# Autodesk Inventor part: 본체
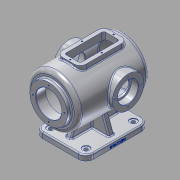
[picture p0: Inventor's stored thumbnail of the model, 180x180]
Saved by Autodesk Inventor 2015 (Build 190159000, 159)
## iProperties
Created: 2021-11
Part Number: 본체
Material: 알루미늄 6061
Document SubType Name: Modeling
Designer: 102879
Density: 2.7 g/cm^3
Appearance: 알루미늄 - 평지
Mass: 3642.31 g
Surface Area: 2489.08 cm^2
Volume: 1349 cm^3
Author: 102879
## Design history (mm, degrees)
sketch "스케치3"
  geometry: L1 (-100, 65)-(-100, 0); L2 (75.993, 65)-(-100, 65); L3 (-100, 0)-(100, 0); A1 r 100 centre (0, 0) between (100, 0) and (75.993, 65); 1 further point
  constraints: 6 end point, 2 horizontal, 2 point on circle, 1 centre point, 1 coincident, 1 midpoint, 1 vertical
  dimensions: "d5" = 100 radius of A1; "d6" = 65 distance from line of point (0, 0) L2; "d10" = 200 dimension on A1 L1
revolve "회전1" sketch "스케치3" stored, may be unused: angle "d11" = 90 deg
sketch "스케치4"
  geometry: C1 r 65 at (0, 0) reference; C2 r 47.5 at (0, 0)
  constraints: 1 centre point, 1 coincident
  dimensions: "d12" = 95 diameter of C2
extrude "돌출2" join sketch "스케치4" distance "d13" = 10; taper "d14" = 0 deg
node "작업 평면1"
sketch "스케치5"
  geometry: L1 (-30, -60)-(30, -60); L2 (30, -60)-(30, 60); L3 (30, 60)-(-30, 60); L4 (-30, 60)-(-30, -60); L5 (-47.5, -110)-(47.5, -110) reference; 1 further point
  constraints: 8 end point, 2 parallel, 1 horizontal, 1 perpendicular
  dimensions: "d16" = 120 distance of L3.end L1.start; "d17" = 60 distance of L1.start L1.end; "d18" = 30 distance from line of L4 point (0, 0); "d26" = 50 distance between parallel lines of L5 L1
extrude "돌출3" join sketch "스케치5" stored distance "d20" = 10; taper "d21" = 0 deg
node "작업 평면2"
sketch "스케치8"
  geometry: L1 (-110, 47.5)-(-100, 47.5) reference; L2 (-100, 47.5)-(-100, 65) reference; L3 (-100, 65)-(-60, 65) reference; L4 (-60, 65)-(-60, 70) reference; L5 (-60, 70)-(60, 70) reference; L6 (60, 70)-(60, 65) reference; L7 (60, 65)-(75.993, 65) reference; L8 (75.993, -65)-(-100, -65) reference; L9 (-100, -65)-(-100, -47.5) reference; L10 (-100, -47.5)-(-110, -47.5) reference; L11 (-110, -47.5)-(-110, 47.5) reference; C1 r 40 at (17, 0); A1 r 100 centre (0, 0) between (75.993, -65) and (75.993, 65) reference; 1 further point
  constraints: 1 centre point, 1 horizontal alignment
  dimensions: "d28" = 80 diameter of C1; "d29" = 127 distance from line of L11 C1.centre
extrude "돌출5" join sketch "스케치8" stored distance "d30" = 150; taper "d31" = 0 deg
sketch "스케치9"
  geometry: L1 (-65, -80)-(65, -80); L2 (65, -80)-(65, 80); L3 (65, 80)-(-65, 80); L4 (-65, 80)-(-65, -80); L5 (-30, -60)-(30, -60) reference; L6 (30, 60)-(-30, 60) reference; 1 further point
  constraints: 8 end point, 2 parallel, 1 horizontal, 1 perpendicular
  dimensions: "d32" = 160 distance of L1.end L2.end; "d33" = 130 distance of L1.start L1.end; "d34" = 65 distance from line of point (0, 0) L2; "d35" = 20 distance between parallel lines of L5 L1; "d36" = 20 distance between parallel lines of L6 L3 (derived)
extrude "돌출6" join sketch "스케치9" distance "d37" = 14; taper "d38" = 0 deg
node "작업 평면3"
sketch "스케치10"
  geometry: L1 (51.397, 114)-(78.603, 114); L2 (78.603, 114)-(115, 14); L3 (130, 14)-(0, 14) reference; L4 (51.397, 114)-(15, 14); L5 (15, 14)-(115, 14); L6 (0, 0)-(0, 14) reference; L7 (130, 0)-(130, 14) reference; 1 further point
  constraints: 8 end point, 2 collinear, 1 horizontal, 1 midpoint
  dimensions: "d41" = 100 distance of L2.end L4.end; "d42" = 20 deg angle of L4 L6; "d43" = 20 deg angle of L7 L2; "d44" = 50 horizontal distance of point (65, 114) L2.end
extrude "돌출7" join sketch "스케치10" stored distance "d45" = 14; taper "d46" = 0 deg
sketch "스케치11"
  geometry: L1 (-23.603, 0)-(-60, -100); L2 (-23.603, 0)-(23.603, 0); L3 (23.603, 0)-(60, -100); L4 (-60, -100)-(60, -100); L5 (80, -100)-(-80, -100) reference; L6 (7, -100)-(7, -55.515) reference; 1 further point
  constraints: 8 end point, 2 horizontal, 1 collinear, 1 midpoint
  dimensions: "d47" = 120 distance of L1.end L3.end; "d48" = 110 deg angle of L5 L3; "d49" = 110 deg angle of L5 L1; "d50" = 53 distance from line of L6 L3.end
extrude "돌출8" join sketch "스케치11" stored distance "d51" = 14; taper "d52" = 0 deg
sketch "스케치12"
  geometry: L1 (-110, 47.5)-(-100, 47.5) reference; L2 (-100, 47.5)-(-100, 65) reference; L3 (-100, 65)-(-60, 65) reference; L4 (-60, 65)-(-60, 70) reference; L5 (-60, 70)-(60, 70) reference; L6 (60, 70)-(60, 65) reference; L7 (60, 65)-(75.993, 65) reference; L8 (75.993, -65)-(47.261, -65) reference; L9 (47.261, -65)-(60, -100) reference; L10 (60, -100)-(80, -100) reference; L11 (80, -100)-(80, -114) reference; L12 (80, -114)-(-80, -114) reference; L13 (-80, -114)-(-80, -100) reference; L14 (-80, -100)-(-60, -100) reference; L15 (-60, -100)-(-47.261, -65) reference; L16 (-47.261, -65)-(-100, -65) reference; L17 (-100, -65)-(-100, -47.5) reference; L18 (-100, -47.5)-(-110, -47.5) reference; L19 (-110, -47.5)-(-110, 47.5) reference; L20 (71.239, 55)-(-85, 55); L21 (-85, 55)-(-85, 0); L22 (-85, 0)-(90, 0); A1 r 100 centre (0, 0) between (75.993, -65) and (75.993, 65) reference; A2 r 90 centre (0, 0) between (90, 0) and (71.239, 55)
  constraints: 6 end point, 2 horizontal, 2 point on circle, 1 centre point, 1 perpendicular, 1 point on line
  dimensions: "d53" = 10 radial gap between concentric circles of A1 A2; "d54" = 10 distance between parallel lines of L7 L20; "d55" = 25 distance between parallel lines of L19 L21
revolve "회전2" sketch "스케치12" stored, may be unused: angle "d56" = 90 deg
sketch "스케치13"
  geometry: C1 r 47.5 at (0, 0) reference; C2 r 32.5 at (0, 0)
  constraints: 1 centre point, 1 coincident
  dimensions: "d57" = 65 diameter of C2
extrude "돌출9" cut sketch "스케치13" distance "d58" = 25; taper "d59" = 0 deg
sketch "스케치14"
  geometry: C1 r 40 at (0, 0) reference; 1 further point
hole "구멍1" sketch "스케치14" at (0, 0) diameter "d61" = 42; stored, may be unused: countersink angle "d65" = 90 deg, drill point angle "d67" = 118 deg; dims "d62" = 6, "d63" = 52, "d64" = 18, "d66" = 8
sketch "스케치15"
  geometry: C1 r 21 at (0, 0) reference; C2 r 40 at (0, 0) reference; C3 r 26 at (0, 0); 1 further point
  constraints: 1 centre point, 1 coincident
  dimensions: "d68" = 52 diameter of C3
extrude "돌출10" cut sketch "스케치15" distance "d69" = 18; taper "d70" = 0 deg
sketch "스케치16"
  geometry: L1 (-30, -60)-(30, -60) reference; L2 (30, -60)-(30, 60) reference; L3 (30, 60)-(-30, 60) reference; L4 (-30, 60)-(-30, -60) reference; L5 (-20, -50)-(20, -50); L6 (20, -50)-(20, 50); L7 (20, 50)-(-20, 50); L8 (-20, 50)-(-20, -50); 1 further point
  constraints: 8 end point, 3 other
  dimensions: "d71" = 10 distance between parallel lines of L4 L8
extrude "돌출11" cut sketch "스케치16" distance "d72" = 30; taper "d73" = 0 deg
fillet "모깎기1" dims "d74" = 5
fillet "모깎기2" dims "d75" = 15
fillet "모깎기3" dims "d76" = 10
fillet "모깎기4" dims "d77" = 3
fillet "모깎기5" dims "d78" = 20
fillet "모깎기6" dims "d79" = 3
sketch "스케치17"
  geometry: C1 r 32.5 at (0, 0) reference; 1 further point
  constraints: 1 vertical alignment
  dimensions: "d80" = 40 distance of C1.centre point (0, 40)
hole "구멍2" sketch "스케치17" at (0, 40) diameter "d81" = 3.242; stored, may be unused: countersink angle "d85" = 90 deg, drill point angle "d87" = 118 deg; dims "d82" = 11, "d83" = 52, "d84" = 18, "d86" = 13
sketch "스케치18"
  geometry: C1 r 26 at (0, 0) reference; 2 further points
  constraints: 1 horizontal alignment
  dimensions: "d91" = 32.5 distance of C1.centre point (-32.5, 0)
hole "구멍3" sketch "스케치18" at (-32.5, 0) diameter "d92" = 3.242; stored, may be unused: countersink angle "d96" = 90 deg, drill point angle "d98" = 118 deg; dims "d93" = 8, "d94" = 52, "d95" = 18, "d97" = 11.8
sketch "스케치19"
  geometry: L1 (15, 60)-(-15, 60) reference; 2 further points
  constraints: 1 vertical alignment
  dimensions: "d102" = 5 distance from line of L1 point (0, 55)
hole "구멍4" sketch "스케치19" at (0, 55) diameter "d103" = 3.242; stored, may be unused: countersink angle "d107" = 90 deg, drill point angle "d109" = 118 deg; dims "d104" = 9, "d105" = 52, "d106" = 18, "d108" = 11
sketch "스케치20"
  geometry: C1 r 1.621 at (0, -55) reference; 2 further points
  dimensions: "d113" = 25 distance of point (0, 0) point (-25, 0); "d114" = 55 vertical distance of C1.centre point (-25, 0)
hole "구멍5" sketch "스케치20" at (-25, 0) diameter "d115" = 3.242; stored, may be unused: countersink angle "d119" = 90 deg, drill point angle "d121" = 118 deg; dims "d116" = 9, "d117" = 52, "d118" = 18, "d120" = 11
sketch "스케치21"
  geometry: A1 r 20 centre (45, -60) between (45, -80) and (65, -60) reference; 1 further point
hole "구멍6" sketch "스케치21" at (45, -60) diameter "d125" = 9; stored, may be unused: countersink angle "d129" = 90 deg, drill point angle "d131" = 118 deg; dims "d126" = 9, "d127" = 18, "d128" = 2, "d130" = 9
fillet "모깎기7" dims "d138" = 3
sketch "스케치22"
  geometry: L1 (0, 0)-(0, 120) reference; L2 (-11, 120)-(0, 120) reference; 2 further points
  constraints: 1 other
  dimensions: "d139" = 5 distance from line of L1 point (-5, 60); "d140" = 60 distance from line of L2 point (-5, 60)
feature "엠보싱1" sketch "스케치22" dims "d20" = 10, "d141" = 0.5, "d142" = 0
chamfer "모따기1" distance "d143" = 1; stored, may be unused: second distance "d144" = 2, angle "d145" = 45 deg
fillet "모깎기8" dims "d146" = 3
node "솔리드2"
pattern_circular "원형 패턴1" dims angle "d89" = 360 deg
pattern_circular "원형 패턴2" dims angle "d100" = 360 deg
mirror "대칭1"
pattern_linear "직사각형 패턴1" dims "d112" = 110
pattern_linear "직사각형 패턴2" dims "d124" = 50
pattern_linear "직사각형 패턴3" dims "d134" = 90
node "절단 모서리 투영1"
node "절단 모서리 투영2"
other parameters: "d25" = -114
